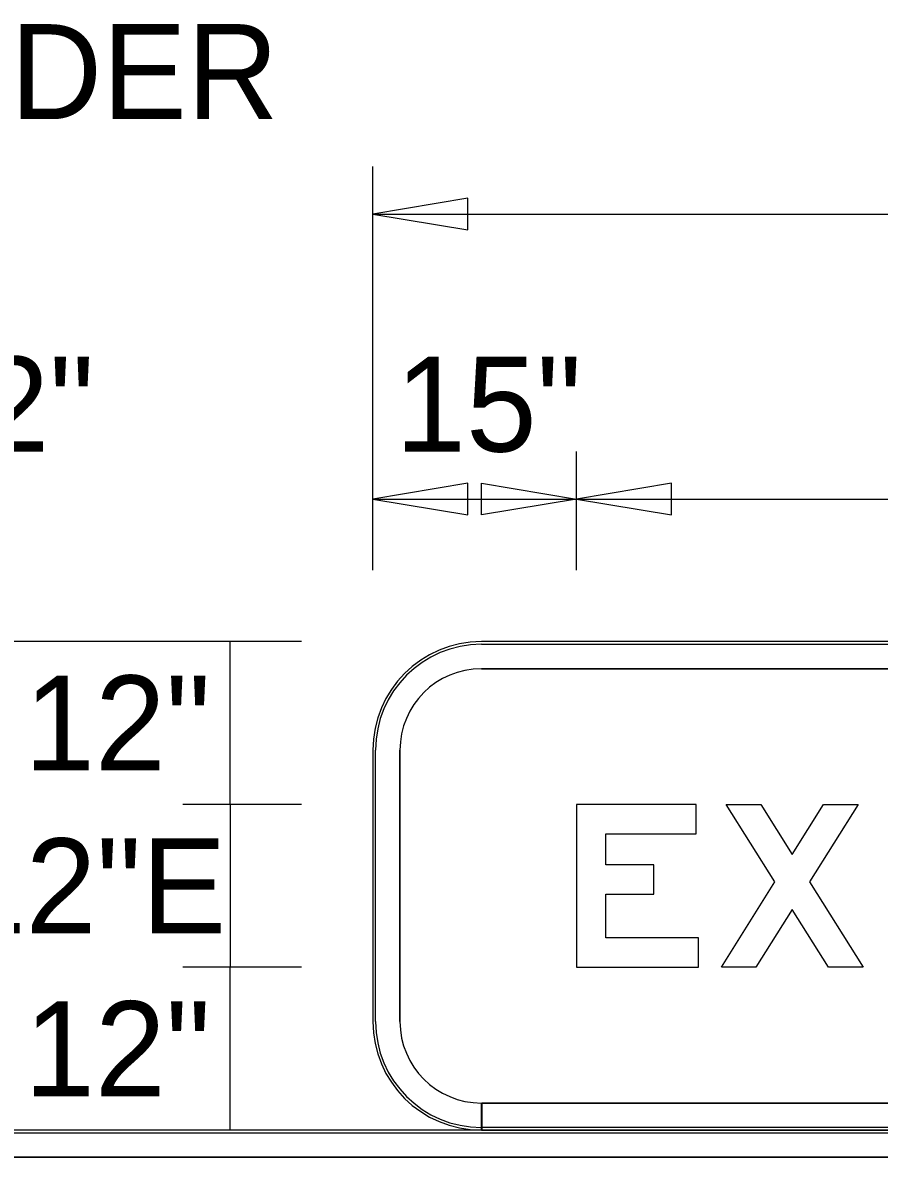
# Model space of a CAD drawing. Extents: x 2149934 to 2150188, y 145114 to 145238.
# Drawn here: x 2150092.63 to 2150097.89, y 145202.28 to 145209.25 of the extents above; entities that cross this region are included whole.
import ezdxf

# ---------------------------------------------------------------- set-up
doc = ezdxf.new("R2010")
doc.units = 0
for name, color, linetype in [('GSBWFILL', 7, 'Continuous'), ('GSCOLORFILL', 7, 'Continuous'), ('GSDIMS', 7, 'Continuous'), ('GSOUTLINE', 7, 'Continuous')]:
    doc.layers.add(name, color=color, linetype=linetype)

msp = doc.modelspace()

# ---------------------------------------------------------------- linework, layer by layer
at = {"layer": 'GSBWFILL'}
for p, q in [((2150107.112, 145205.445), (2150095.4451, 145205.445)), ((2150095.4451, 145205.2784), (2150107.112, 145205.2784)), ((2150094.7785, 145204.7784), (2150094.7785, 145203.1114)), ((2150094.9451, 145203.1114), (2150094.9451, 145204.7784)), ((2150095.4451, 145202.4447), (2150095.4451, 145202.6114)), ((2150107.112, 145202.6114), (2150095.4468, 145202.6114)), ((2150095.4468, 145202.6114), (2150095.4468, 145202.4447)), ((2150107.2786, 145202.4447), (2150088.7786, 145202.4447)), ((2150095.4468, 145202.4447), (2150107.112, 145202.4447)), ((2150088.7786, 145202.2781), (2150107.2786, 145202.2781))]:
    msp.add_line(p, q, dxfattribs=at)
for points in [[(2150096.7786, 145203.625), (2150096.2086, 145203.625), (2150096.2086, 145203.894), (2150096.5036, 145203.894), (2150096.5036, 145204.074), (2150096.2086, 145204.074), (2150096.2086, 145204.265), (2150096.7636, 145204.265), (2150096.7636, 145204.445), (2150096.0286, 145204.445), (2150096.0286, 145203.445), (2150096.7786, 145203.445)], [(2150097.5761, 145203.445), (2150097.3536, 145203.7996), (2150097.1311, 145203.445), (2150096.9186, 145203.445), (2150097.2473, 145203.9689), (2150096.9486, 145204.445), (2150097.1611, 145204.445), (2150097.3536, 145204.1382), (2150097.5461, 145204.445), (2150097.7586, 145204.445), (2150097.4598, 145203.9689), (2150097.7886, 145203.445)]]:
    msp.add_lwpolyline(points, close=True, dxfattribs=at)
for centre, radius, start, end in [((2150095.4451, 145204.7784), 0.6667, 90, 180), ((2150095.4451, 145204.7784), 0.5, 90, 180), ((2150095.4451, 145203.1114), 0.6667, 180, 270), ((2150095.4451, 145203.1114), 0.5, 180, 270)]:
    msp.add_arc(centre, radius, start, end, dxfattribs=at)
at = {"layer": 'GSCOLORFILL'}
for p, q in [((2150107.112, 145205.445), (2150095.4451, 145205.445)), ((2150107.112, 145205.445), (2150095.4451, 145205.445)), ((2150107.112, 145205.445), (2150095.4451, 145205.445)), ((2150095.4451, 145205.4284), (2150107.112, 145205.4284)), ((2150095.4451, 145205.2784), (2150107.112, 145205.2784)), ((2150094.7785, 145204.7784), (2150094.7785, 145203.1114)), ((2150094.7785, 145204.7784), (2150094.7785, 145203.1114)), ((2150094.7785, 145204.7784), (2150094.7785, 145203.1114)), ((2150094.7951, 145203.1114), (2150094.7951, 145204.7784)), ((2150094.9451, 145203.1114), (2150094.9451, 145204.7784)), ((2150095.4451, 145202.4447), (2150095.4451, 145202.6114)), ((2150107.112, 145202.6114), (2150095.4468, 145202.6114)), ((2150095.4468, 145202.6114), (2150095.4468, 145202.4447)), ((2150107.2786, 145202.4447), (2150088.7786, 145202.4447)), ((2150107.2786, 145202.4447), (2150088.7786, 145202.4447)), ((2150107.2786, 145202.4447), (2150088.7786, 145202.4447)), ((2150095.4451, 145202.4447), (2150095.4451, 145202.4614)), ((2150095.4451, 145202.4447), (2150107.112, 145202.4447)), ((2150107.112, 145202.4614), (2150095.4453, 145202.4614)), ((2150095.4453, 145202.4614), (2150095.4453, 145202.4447)), ((2150095.4453, 145202.4447), (2150107.112, 145202.4447)), ((2150095.4468, 145202.4447), (2150107.112, 145202.4447)), ((2150088.7786, 145202.4281), (2150107.2786, 145202.4281)), ((2150088.7786, 145202.2781), (2150107.2786, 145202.2781))]:
    msp.add_line(p, q, dxfattribs=at)
for points in [[(2150096.7786, 145203.625), (2150096.2086, 145203.625), (2150096.2086, 145203.894), (2150096.5036, 145203.894), (2150096.5036, 145204.074), (2150096.2086, 145204.074), (2150096.2086, 145204.265), (2150096.7636, 145204.265), (2150096.7636, 145204.445), (2150096.0286, 145204.445), (2150096.0286, 145203.445), (2150096.7786, 145203.445)], [(2150097.5761, 145203.445), (2150097.3536, 145203.7996), (2150097.1311, 145203.445), (2150096.9186, 145203.445), (2150097.2473, 145203.9689), (2150096.9486, 145204.445), (2150097.1611, 145204.445), (2150097.3536, 145204.1382), (2150097.5461, 145204.445), (2150097.7586, 145204.445), (2150097.4598, 145203.9689), (2150097.7886, 145203.445)]]:
    msp.add_lwpolyline(points, close=True, dxfattribs=at)
for centre, radius, start, end in [((2150095.4451, 145204.7784), 0.6667, 90, 180), ((2150095.4451, 145204.7784), 0.6667, 90, 180), ((2150095.4451, 145204.7784), 0.6667, 90, 180), ((2150095.4451, 145204.7784), 0.65, 90, 180), ((2150095.4451, 145204.7784), 0.5, 90, 180), ((2150095.4451, 145203.1114), 0.6667, 180, 270), ((2150095.4451, 145203.1114), 0.6667, 180, 270), ((2150095.4451, 145203.1114), 0.6667, 180, 270), ((2150095.4451, 145203.1114), 0.65, 180, 270), ((2150095.4451, 145203.1114), 0.5, 180, 270)]:
    msp.add_arc(centre, radius, start, end, dxfattribs=at)
at = {"layer": 'GSDIMS'}
for p, q in [((2150094.7784, 145207.6326), (2150094.7784, 145208.3618)), ((2150094.7784, 145208.0701), (2150107.7787, 145208.0701)), ((2150094.7784, 145205.8826), (2150094.7784, 145207.6326)), ((2150094.7784, 145205.8826), (2150094.7784, 145206.6118)), ((2150096.0286, 145205.8826), (2150096.0286, 145206.6118)), ((2150096.0286, 145205.8826), (2150096.0286, 145206.6118)), ((2150094.7784, 145206.3201), (2150096.0286, 145206.3201)), ((2150096.0286, 145206.3201), (2150106.5261, 145206.3201)), ((2150094.3409, 145205.4451), (2150090.8409, 145205.4451)), ((2150094.3409, 145205.4451), (2150093.6117, 145205.4451)), ((2150093.9034, 145204.445), (2150093.9034, 145205.4451)), ((2150094.3409, 145204.445), (2150093.6117, 145204.445)), ((2150094.3409, 145204.445), (2150093.6117, 145204.445)), ((2150093.9034, 145204.445), (2150093.9034, 145203.445)), ((2150094.3409, 145203.445), (2150093.6117, 145203.445)), ((2150094.3409, 145203.445), (2150093.6117, 145203.445)), ((2150093.9034, 145202.4447), (2150093.9034, 145203.445)), ((2150094.3409, 145202.4447), (2150090.8409, 145202.4447)), ((2150094.3409, 145202.4447), (2150093.6117, 145202.4447))]:
    msp.add_line(p, q, dxfattribs=at)
for points in [[(2150094.7784, 145208.0701), (2150095.3617, 145207.9729), (2150095.3617, 145208.1673)], [(2150094.7784, 145206.3201), (2150095.3617, 145206.2229), (2150095.3617, 145206.4173)], [(2150096.0286, 145206.3201), (2150095.4453, 145206.2229), (2150095.4453, 145206.4173)], [(2150096.0286, 145206.3201), (2150096.6119, 145206.2229), (2150096.6119, 145206.4173)]]:
    msp.add_lwpolyline(points, close=True, dxfattribs=at)
at = {"layer": 'GSOUTLINE'}
for p, q in [((2150107.112, 145205.445), (2150095.4451, 145205.445)), ((2150107.112, 145205.2784), (2150095.4451, 145205.2784)), ((2150094.7785, 145204.7784), (2150094.7785, 145203.1114)), ((2150094.9451, 145204.7784), (2150094.9451, 145203.1114)), ((2150095.4451, 145202.6114), (2150107.112, 145202.6114)), ((2150107.2786, 145202.4447), (2150088.7786, 145202.4447)), ((2150095.4451, 145202.4447), (2150107.112, 145202.4447)), ((2150107.2786, 145202.2781), (2150088.7786, 145202.2781))]:
    msp.add_line(p, q, dxfattribs=at)
for points in [[(2150096.7786, 145203.625), (2150096.2086, 145203.625), (2150096.2086, 145203.894), (2150096.5036, 145203.894), (2150096.5036, 145204.074), (2150096.2086, 145204.074), (2150096.2086, 145204.265), (2150096.7636, 145204.265), (2150096.7636, 145204.445), (2150096.0286, 145204.445), (2150096.0286, 145203.445), (2150096.7786, 145203.445)], [(2150097.5761, 145203.445), (2150097.3536, 145203.7996), (2150097.1311, 145203.445), (2150096.9186, 145203.445), (2150097.2473, 145203.9689), (2150096.9486, 145204.445), (2150097.1611, 145204.445), (2150097.3536, 145204.1382), (2150097.5461, 145204.445), (2150097.7586, 145204.445), (2150097.4598, 145203.9689), (2150097.7886, 145203.445)]]:
    msp.add_lwpolyline(points, close=True, dxfattribs=at)
for centre, radius, start, end in [((2150095.4451, 145204.7784), 0.6667, 90, 180), ((2150095.4451, 145204.7784), 0.5, 90, 180), ((2150095.4451, 145203.1114), 0.6667, 180, 270), ((2150095.4451, 145203.1114), 0.5, 180, 270)]:
    msp.add_arc(centre, radius, start, end, dxfattribs=at)

# ---------------------------------------------------------------- texts
at = {"layer": 'GSDIMS'}
for s, p in [('BORDER', (2150090.8622, 145208.6535)), ('TH=2"', (2150090.8622, 145206.6118)), ('15"', (2150094.9169, 145206.6118)), ('12"', (2150092.6386, 145204.6534)), ('12"E', (2150092.2131, 145203.6533)), ('12"', (2150092.6386, 145202.6532))]:
    msp.add_text(s, height=0.58333, dxfattribs=at).set_placement(p)

doc.saveas('drawing.dxf')
